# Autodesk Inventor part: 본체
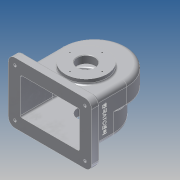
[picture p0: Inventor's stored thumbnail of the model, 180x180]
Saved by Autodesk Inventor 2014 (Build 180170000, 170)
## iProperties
Created: 2017-11
Part Number: 본체
Material: 알루미늄 6061
Document SubType Name: Modeling
Designer: kb543-05
Density: 2.71 g/cm^3
Appearance: 알루미늄 - 평지
Mass: 1079.49 g
Surface Area: 1182.07 cm^2
Volume: 398.334 cm^3
Author: kb543-05
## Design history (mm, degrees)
sketch "스케치1"
  geometry: L1 (58, 0)-(58, -65); L2 (58, -65)-(-58, -65); L3 (-58, -65)-(-58, 0); A1 r 58 centre (0, 0) between (58, 0) and (-58, 0); 1 further point
  constraints: 6 end point, 2 perpendicular, 2 point on circle, 2 tangent, 1 centre point, 1 coincident, 1 vertical
  dimensions: "d0" = 116 diameter of A1; "d1" = 65 distance of L1.start L1.end
extrude "돌출1" new body sketch "스케치1" distance "d2" = 38; taper "d3" = 0 deg
sketch "스케치2"
  geometry: L1 (-58, -65)-(-58, 0) reference; L2 (58, -65)-(-58, -65) reference; L3 (58, 0)-(58, -65) reference; L4 (-58, -23)-(-58, -65); L5 (58, -65)-(58, -23); A1 r 58 centre (0, 0) between (58, 0) and (-58, 0) reference; A2 r 58 centre (0, -23) between (58, -23) and (-58, -23)
  constraints: 4 end point, 2 point on circle, 2 point on line, 1 centre point, 1 parallel, 1 vertical alignment
  dimensions: "d4" = 116 diameter of A2; "d5" = 42 distance from line of A2.centre L2
extrude "돌출2" join sketch "스케치2" distance "d6" = 38; taper "d7" = 0 deg
feature "쉘1" dims "d8" = 5
sketch "스케치3"
  geometry: L1 (133, -93)-(-17, -93); L2 (-17, -93)-(-17, 17); L3 (-17, 17)-(133, 17); L4 (133, 17)-(133, -93); L5 (133, -93)-(-17, 17); L6 (-17, -93)-(133, 17); 1 further point
  constraints: 12 end point, 2 midpoint, 2 parallel, 1 horizontal, 1 perpendicular
  dimensions: "d9" = 150 distance of L2.end L3.end; "d10" = 110 distance of L1.end L2.end
extrude "돌출3" join sketch "스케치3" distance "d11" = 15; taper "d12" = 0 deg
sketch "스케치4"
  geometry: L1 (5, -5)-(111, -5) reference; L2 (5, -71)-(5, -5) reference; L3 (111, -71)-(5, -71) reference; L4 (111, -71)-(111, -5) reference; 1 further point
extrude "돌출4" cut sketch "스케치4" distance "d13" = 20; taper "d14" = 0 deg
fillet "모깎기1" dims "d15" = 12
sketch "스케치6"
  geometry: A1 r 12 centre (-5, 81) between (-5, 93) and (-17, 81) reference; A2 r 12 centre (-5, -5) between (-17, -5) and (-5, -17) reference; A3 r 12 centre (121, -5) between (121, -17) and (133, -5) reference; A4 r 12 centre (121, 81) between (133, 81) and (121, 93) reference; 1 further point
hole "구멍1" sketch "스케치6" at (-5, 81), (121, 81), (121, -5), (-5, -5) diameter "d16" = 5; stored, may be unused: countersink angle "d20" = 90 deg, drill point angle "d22" = 118 deg; dims "d17" = 6, "d18" = 12, "d19" = 5, "d21" = 8
sketch "스케치7"
  geometry: L1 (63, -80)-(-63, -80) reference; C1 r 37.5 at (0, -15); A1 r 58 centre (0, 0) between (58, 0) and (-58, 0) reference
  constraints: 1 centre point, 1 vertical alignment
  dimensions: "d23" = 75 diameter of C1; "d24" = 65 distance from line of C1.centre L1
extrude "돌출5" join sketch "스케치7" distance "d25" = 9; taper "d26" = 0 deg
sketch "스케치8"
  geometry: L1 (63, -80)-(-63, -80) reference; C1 r 31 at (0, -15); 1 further point
  constraints: 1 centre point, 1 vertical alignment
  dimensions: "d27" = 62 diameter of C1; "d28" = 65 distance from line of C1.centre L1
extrude "돌출6" join sketch "스케치8" distance "d29" = 10; taper "d30" = 0 deg
sketch "스케치9"
  geometry: C1 r 31 at (0, 0) reference; C2 r 16 at (0, 0); 1 further point
  constraints: 1 centre point, 1 coincident
  dimensions: "d31" = 32 diameter of C2
extrude "돌출7" cut sketch "스케치9" stored distance "d32" = 10; taper "d33" = 0 deg
node "작업 평면1"
sketch "스케치10"
  geometry: L1 (116, 0)-(0, 0) reference; C1 r 6 at (58, -19); 1 further point
  constraints: 1 centre point, 1 vertical alignment
  dimensions: "d35" = 12 diameter of C1; "d36" = 19 distance from line of C1.centre L1
extrude "돌출8" join sketch "스케치10" stored distance "d37" = 10; taper "d38" = 0 deg
sketch "스케치11"
  geometry: C1 r 6 at (0, 0) reference; 1 further point
hole "구멍2" sketch "스케치11" at (0, 0) diameter "d39" = 4.459; stored, may be unused: countersink angle "d43" = 90 deg, drill point angle "d45" = 118 deg; dims "d40" = 6, "d41" = 12, "d42" = 5, "d44" = 8
sketch "스케치12" dims "d46" = 58
  geometry: C1 r 16 at (0, 0) reference; C2 r 37.5 at (0, 0) reference; 6 further points
  constraints: 2 vertical alignment, 1 coincident, 7 other
  dimensions: "d49" = 360 deg dimension on C1.centre point (0, 29) (derived)
hole "구멍3" sketch "스케치12" at (0, 29), (-29, 0), (0, -29), (29, 0) diameter "d51" = 2.459; stored, may be unused: countersink angle "d55" = 90 deg, drill point angle "d57" = 118 deg; dims "d52" = 6, "d53" = 12, "d54" = 5, "d56" = 8
sketch "스케치13" dims "d58" = 52
  geometry: C1 r 16 at (0, 0) reference; C2 r 31 at (0, 0) reference; 6 further points
  constraints: 2 vertical alignment, 1 coincident, 7 other
  dimensions: "d61" = 360 deg dimension on C1.centre point (0, 26) (derived)
hole "구멍4" sketch "스케치13" at (0, 26), (-26, 0), (0, -26), (26, 0) diameter "d63" = 2.459; stored, may be unused: countersink angle "d67" = 90 deg, drill point angle "d69" = 118 deg; dims "d64" = 6, "d65" = 12, "d66" = 5, "d68" = 8
sketch "스케치14"
  geometry: L1 (0, -65)-(0, 0) reference; L2 (13.113, -36.398)-(62.887, -36.398); L3 (62.887, -36.398)-(62.887, -43.602); L4 (62.887, -43.602)-(13.113, -43.602); L5 (13.113, -43.602)-(13.113, -36.398); L6 (81, -80)-(-5, -80) reference; 3 further points
  constraints: 2 midpoint, 1 horizontal alignment, 1 vertical alignment, 2 other
  dimensions: "d70" = 40 distance from line of L6 point (38, -40); "d71" = 38 distance from line of point (38, -40) L1
feature "엠보싱1" sketch "스케치14" dims "d72" = 0.5, "d73" = 0
fillet "모깎기2" dims "d74" = 8
fillet "모깎기3" dims "d75" = 3
fillet "모깎기4" dims "d76" = 3
chamfer "모따기1" distance "d77" = 1; stored, may be unused: second distance "d78" = 2, angle "d79" = 45 deg
node "솔리드1"
other parameters: "d34" = -144
